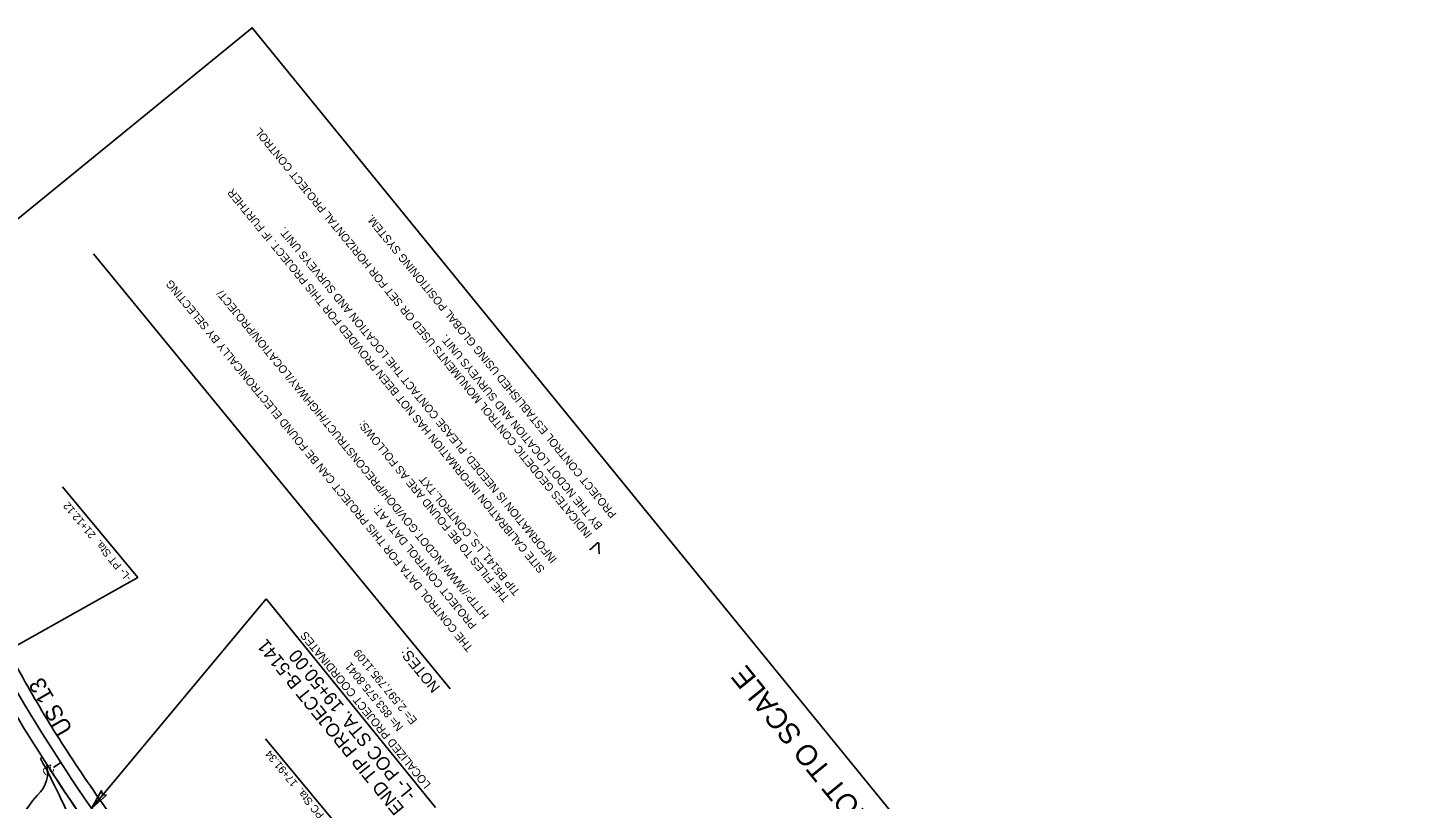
# Model space of a CAD drawing. Extents: x 2596159 to 2598075, y 851667 to 853493.
# Drawn here: x 2596820 to 2597951, y 852864 to 853493 of the extents above; entities that cross this region are included whole.
import ezdxf

# ---------------------------------------------------------------- set-up
doc = ezdxf.new("R2010")
doc.units = 0
for name, color, linetype in [('CTL Sheet Notes CELL', 7, 'Continuous'), ('CTL Sheet Text', 7, 'Continuous'), ('Default', 7, 'Continuous'), ('Exist Roads EOP', 7, 'Continuous'), ('Exist Roads Soil', 7, 'Continuous'), ('Old_Level_18', 7, 'Continuous'), ('Old_Level_2', 7, 'Continuous'), ('Old_Level_40', 7, 'Continuous'), ('Prop Dimension', 7, 'Continuous'), ('Prop Dimension Text', 7, 'Continuous'), ('Prop Horizontal Alignment', 7, 'Continuous'), ('Prop Horizontal Alignment Station Label', 7, 'Continuous'), ('Prop Horizontal Alignment Tick Label', 7, 'Continuous'), ('Prop Horizontal Alignment Tick Large', 7, 'Continuous'), ('Prop Shade Medium', 7, 'Continuous'), ('Prop Terminator CELL', 7, 'Continuous')]:
    doc.layers.add(name, color=color, linetype=linetype)

msp = doc.modelspace()

# ---------------------------------------------------------------- linework, layer by layer
at = {"layer": 'CTL Sheet Notes CELL'}
msp.add_line((2597164.2, 852954.1), (2596873.5, 853308.6), dxfattribs=at)
at = {"layer": 'Exist Roads EOP'}
for points in [[(2597043.4, 852655.6), (2596986.4, 852724.5), (2596929.8, 852794.5), (2596890.1, 852847.6), (2596852, 852903.2), (2596819.7, 852956.4), (2596805.9, 852981.4)], [(2597027.8, 852643.1), (2596971.2, 852711.2), (2596914.3, 852781.9), (2596874.4, 852834.9), (2596835.8, 852892.1), (2596798.8, 852952.5), (2596789.2, 852969.7)]]:
    msp.add_spline(points, degree=3, dxfattribs=at)
at = {"layer": 'Exist Roads Soil'}
msp.add_lwpolyline([(2596835.5, 852892.8), (2596836.1, 852887.3), (2596836.2, 852883.6), (2596835.3, 852879.4), (2596834.2, 852876.4), (2596832.4, 852872.8), (2596830.3, 852870.1), (2596827.6, 852867.2), (2596823.7, 852862.8), (2596820.7, 852858.5), (2596816.4, 852852.7), (2596812.8, 852847.9), (2596810.2, 852842.6), (2596804.2, 852831), (2596792.3, 852813.7), (2596790.4, 852810.2)], dxfattribs=at)
at = {"layer": 'Old_Level_18'}
msp.add_lwpolyline([(2596922.8, 851929.1), (2596189, 852829.3), (2597002.9, 853492.7), (2597950.7, 852330), (2597136.8, 851666.6), (2596922.8, 851929.1)], dxfattribs=at)
at = {"layer": 'Prop Dimension'}
for points in [[(2596871.9, 852856.6), (2597014.2, 853027.3)], [(2597152.2, 852857.5), (2597014.2, 853027.3)]]:
    msp.add_lwpolyline(points, dxfattribs=at)
at = {"layer": 'Prop Horizontal Alignment'}
msp.add_arc((2598178.7, 853756.4), 1586.7, 209.2814, 219.7067, dxfattribs=at)
at = {"layer": 'Prop Horizontal Alignment Station Label'}
for p, q in [((2596909.7, 853044.8), (2596848.3, 853118.7)), ((2596794.8, 852980.4), (2596909.7, 853044.8)), ((2597074.9, 852839.8), (2597013.8, 852913.4))]:
    msp.add_line(p, q, dxfattribs=at)
at = {"layer": 'Prop Horizontal Alignment Tick Large'}
msp.add_line((2596846.9, 852894), (2596840.9, 852890.1), dxfattribs=at)
at = {"layer": 'Prop Shade Medium'}
msp.add_line((2596831.8, 852898.3), (2596830.4, 852897.2), dxfattribs=at)
msp.add_arc((2596179.4, 852547.7), 738.9, 23.1003, 28.2317, dxfattribs=at)
msp.add_open_spline([(2596863.3, 852850.7), (2596853.8, 852864.3), (2596844.7, 852878.2), (2596835.8, 852892.1), (2596834.4, 852894.2), (2596833.1, 852896.3), (2596831.8, 852898.3)], degree=3, dxfattribs=at)
at = {"layer": 'Prop Terminator CELL'}
msp.add_lwpolyline([(2596884.2, 852867.5), (2596871.9, 852856.6), (2596879.9, 852871.1), (2596880.8, 852867.7)], close=True, dxfattribs=at)

# ---------------------------------------------------------------- texts
at = {"layer": 'CTL Sheet Notes CELL'}
for s, height, rotation, p in [('INDICATES GEODETIC CONTROL MONUMENTS USED OR SET FOR HORIZONTAL PROJECT CONTROL', 6.52, 129.2489, (2597280.3, 853080.2)), ('SITE CALIBRATION INFORMATION HAS NOT BEEN PROVIDED FOR THIS PROJECT. IF FURTHER', 6.52, 129.3541, (2597241.7, 853051.7)), ('PROJECT CONTROL ESTABLISHED USING GLOBAL POSITIONING SYSTEM.', 6.52, 129.2489, (2597300.2, 853096.5)), ('INFORMATION IS NEEDED, PLEASE CONTACT THE LOCATION AND SURVEYS UNIT.', 6.52, 129.3541, (2597251.6, 853059.8)), ('   THE CONTROL DATA FOR THIS PROJECT CAN BE FOUND ELECTRONICALLY BY SELECTING', 6.52, 129.3541, (2597187.8, 852982)), ('HTTP://WWW.NCDOT.GOV/DOH/PRECONSTRUCT/HIGHWAY/LOCATION/PROJECT/', 6.52, 129.3541, (2597196.2, 853014.4)), ('BY THE NCDOT LOCATION AND SURVEYS UNIT.', 6.52, 129.2489, (2597288.7, 853087.1)), ('THE FILES TO BE FOUND ARE AS FOLLOWS:', 6.52, 129.3541, (2597212.9, 853028.1)), ('TIP B5141_LS_CONTROL.TXT', 6.52, 129.3541, (2597221.4, 853033.4)), ('PROJECT CONTROL DATA AT:', 6.52, 129.3541, (2597186.2, 853006.2)), ('NOTES:', 8.69, 129.2489, (2597156.5, 852955.4))]:
    msp.add_text(s, height=height, rotation=rotation, dxfattribs=at).set_placement(p)
at = {"layer": 'CTL Sheet Text'}
for s, p in [('LOCALIZED PROJECT COORDINATES', (2597148.8, 852876.2)), ('E= 2,597,795.1109', (2597137.7, 852928.5)), ('N= 853,575.8041', (2597126.4, 852923))]:
    msp.add_text(s, height=6.67, rotation=129.1835, dxfattribs=at).set_placement(p)
at = {"layer": 'Default'}
msp.add_text('US 13', height=13.5, rotation=120.2871, dxfattribs=at).set_placement((2596857, 852921.2))
at = {"layer": 'Old_Level_2'}
msp.add_text('>', height=13.3, rotation=66.9733, dxfattribs=at).set_placement((2597287.2, 853062.2))
at = {"layer": 'Old_Level_40'}
msp.add_text('NOTE: DRAWING NOT TO SCALE', height=16.875, rotation=129.0782, dxfattribs=at).set_placement((2597629.6, 852698.1))
at = {"layer": 'Prop Dimension Text'}
for s, p in [('END TIP PROJECT B-5141', (2597127.3, 852856.7)), ('-L- POC STA. 19+50.00', (2597137, 852868))]:
    msp.add_text(s, height=10.8, rotation=129.1027, dxfattribs=at).set_placement(p)
at = {"layer": 'Prop Horizontal Alignment Station Label'}
for s, rotation, p in [('-L- PT Sta.  21+12.12', 129.8687, (2596904.9, 853044.9)), ('-L- PC Sta.  17+91.34', 129.7067, (2597069.9, 852841.8))]:
    msp.add_text(s, height=6.3, rotation=rotation, dxfattribs=at).set_placement(p)
at = {"layer": 'Prop Horizontal Alignment Tick Label'}
msp.add_text('20', height=6.3, rotation=212.9254, dxfattribs=at).set_placement((2596839, 852893))

doc.saveas('drawing.dxf')
